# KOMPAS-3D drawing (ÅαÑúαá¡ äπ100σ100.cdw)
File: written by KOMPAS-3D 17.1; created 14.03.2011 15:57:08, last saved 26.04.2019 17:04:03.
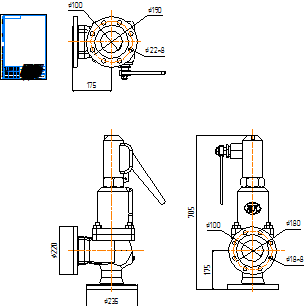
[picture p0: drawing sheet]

Title block, sheet 1: name: Прегран Ду100х100; material: Внимание! Данный продукт является объектом авторского права ООО «Торговый Дом АДЛ». / Запрещается изменение, копирование, распространение / (в том числе путем копирования на другие сайты и ресурсы в Интернете) / или любое иное использование информации и объектов без предварительного / согласия правообладателя (ООО «Торговый Дом АДЛ»).; scale: 1:1; sheets: 1; organisation: ООО "Торговый дом АДЛ"; sheet format: A4; stored path: C:\Users\tra\Desktop\2д чертежи\Предохранительные клапаны ПРЕГРАН\ПРЕГРАН 096\ПРЕГРАН КПП 096-03-40\KOMPAS 2D\Прегран Ду100х100.cdw

Views: Спереди 1, Проекционный вид 5
Dimensions and other numbers on the sheet: 235; 220; 180; 18; 100; 175; 705; 190; 22; 1:1; 1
